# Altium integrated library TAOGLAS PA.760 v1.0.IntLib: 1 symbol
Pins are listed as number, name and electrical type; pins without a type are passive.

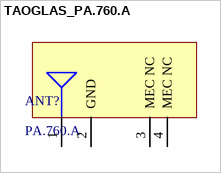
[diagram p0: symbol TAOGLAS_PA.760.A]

## TAOGLAS_PA.760.A
designator ANT?, comment PA.760.A
WARRIOR X Wideband (600-6000MHz) Antenna for 5G NR & 4G Bands; ComponentLibStatus: Created; MFG: Taoglas; Temp_High: +85C; Temp_Low: -40C
footprint TAOGLAS_PA.760.A (WARRIOR X Widebnad  (600-6000MHz) Antenna for 5G NR & 4G Bands)
pins: 1 RF OUT, 2 GND, 3 MEC NC, 4 MEC NC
